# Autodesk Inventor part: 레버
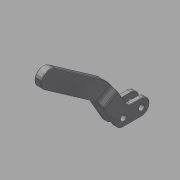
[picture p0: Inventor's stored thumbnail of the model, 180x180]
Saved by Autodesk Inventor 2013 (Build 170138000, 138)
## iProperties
Created: 2017-10
Part Number: 레버
Material: 스테인리스강
Document SubType Name: Modeling
Designer: mduedu
Density: 1 g/cm^3
Author: mduedu
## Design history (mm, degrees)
sketch "스케치1" dims "d0" = 14
  geometry: L1 (7, 0)-(-7, 0); L2 (-7, 0)-(-7, 16); L3 (-7, 16)-(7, 16); L4 (7, 16)-(7, 0); L5 (26.017, 22.938)-(19.017, 35.062); L6 (19.017, 35.062)-(-3.5, 22.062); L7 (-3.5, 22.062)-(3.5, 9.938); L8 (3.5, 9.938)-(26.017, 22.938); L9 (0, 16)-(22.517, 29); L10 (0, 16)-(0, 0); C1 r 7 at (0, 16); 1 further point
  constraints: 20 end point, 5 parallel, 4 midpoint, 2 perpendicular, 2 tangent, 1 centre point, 1 coincident, 1 horizontal, 1 horizontal alignment, 2 other
  dimensions: "d2" = 16 distance of L9.start point (0, 0); "d3" = 120 deg angle of L9 L10; "d4" = 26 distance of L9.start L9.end
extrude "돌출1" new body sketch "스케치1" stored distance "d5" = 13; taper "d6" = 0 deg
sketch "스케치2"
  geometry: L1 (3.5, 15.959)-(9.5, 15.959); L2 (9.5, 15.959)-(9.5, -44.041); L3 (9.5, -44.041)-(3.5, -44.041); L4 (3.5, -44.041)-(3.5, 15.959); L5 (13, 21.959)-(0, 21.959) reference; 2 further points
  constraints: 8 end point, 2 parallel, 1 horizontal, 1 midpoint, 1 perpendicular, 1 vertical alignment
  dimensions: "d7" = 6 distance between parallel lines of L1 L5; "d8" = 60 distance of L1.end L2.end; "d9" = 6 distance of L2.end L3.end
extrude "돌출2" cut sketch "스케치2" stored distance "d10" = 13; taper "d11" = 0 deg
fillet "모깎기1"
sketch "스케치3"
  geometry: L1 (35.591, 31.711)-(68.712, 79.013); L2 (68.712, 79.013)-(56.425, 87.617); L3 (56.425, 87.617)-(20.717, 36.62); L4 (7, 11.959)-(7, 0) reference; L5 (19.017, 35.062)-(26.017, 22.938) reference; L6 (26.017, 22.938)-(7, 11.959) reference; L7 (-3.5, 22.062)-(19.017, 35.062) reference; L8 (35.591, 31.711)-(20.717, 36.62); L9 (28.154, 34.166)-(62.569, 83.315); A1 r 30 centre (11.017, 48.919) between (26.017, 22.938) and (35.591, 31.711); A2 r 5.327 centre (16.353, 39.675) between (19.017, 35.062) and (20.717, 36.62); 1 further point
  constraints: 10 end point, 4 point on circle, 4 tangent, 2 centre point, 2 midpoint, 1 parallel, 1 perpendicular
  dimensions: "d18" = 60 distance of L9.start L9.end; "d22" = 145 deg angle of L9 L4; "d24" = 30 radius of A1; "d39" = 15 distance of L1.end L2.end
extrude "돌출3" join sketch "스케치3" stored distance "d16" = 6; taper "d17" = 0 deg
fillet "모깎기2"
chamfer "모따기1" distance "d26" = 3.5; stored, may be unused: second distance "d27" = 2, angle "d28" = 45 deg
fillet "모깎기3" dims "d29" = 5
fillet "모깎기4" dims "d30" = 5
sketch "스케치4"
  geometry: C1 r 2.5 at (0, 0); C2 r 2.5 at (-16, 0); A1 r 7 centre (-16, 0) between (-22.062, -3.5) and (-16, -7) reference; 1 further point
  constraints: 2 centre point, 2 coincident
  dimensions: "d31" = 5 diameter of C1; "d32" = 5 diameter of C2 (= d31)
extrude "돌출4" cut sketch "스케치4" stored distance "d33" = 6; taper "d34" = 0 deg
fillet "모깎기5" dims "d38" = 0.5
node "작업 평면1"
node "솔리드1"
